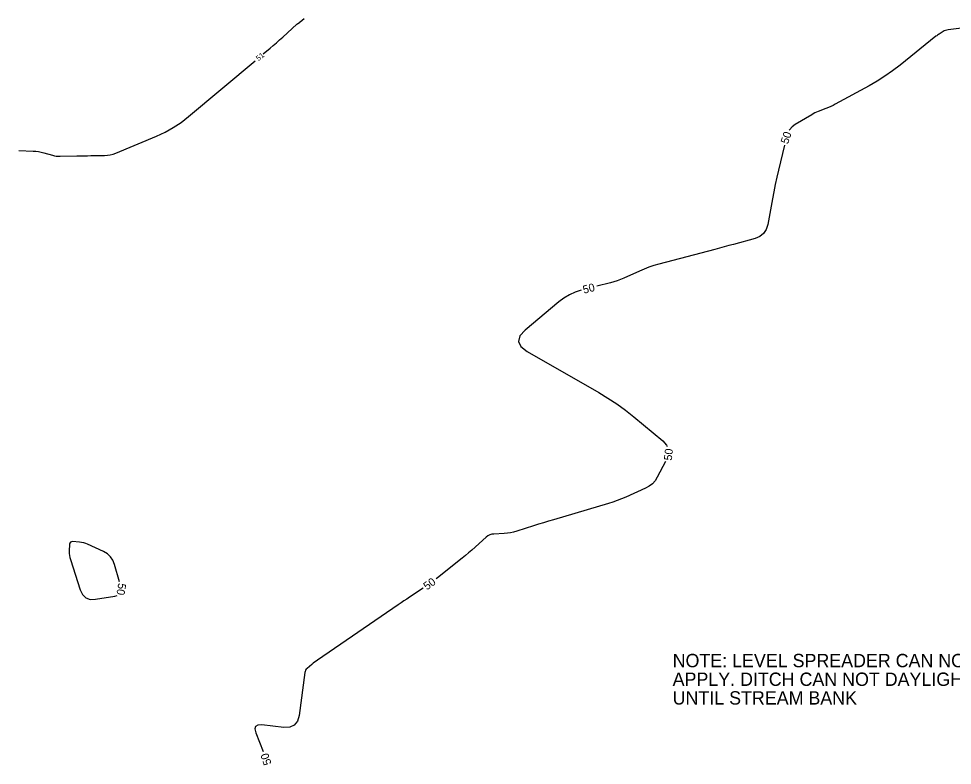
# Model space of a CAD drawing. Extents: x 2384780 to 2405861, y 547869 to 573706.
# Drawn here: x 2391215.6 to 2391565.6, y 553081.3 to 553361.3 of the extents above; entities that cross this region are included whole.
import ezdxf

# ---------------------------------------------------------------- set-up
doc = ezdxf.new("R2010")
doc.units = 0
for name, color, linetype in [('Old_Level_60', 7, 'Continuous'), ('Old_Level_61', 7, 'Continuous'), ('Old_Level_63', 7, 'Continuous')]:
    doc.layers.add(name, color=color, linetype=linetype)

msp = doc.modelspace()

# ---------------------------------------------------------------- linework, layer by layer
at = {"layer": 'Old_Level_60'}
for points in [[(2391307.291, 553348.0905), (2391309.83275, 553350.222), (2391311.03475, 553351.2415), (2391312.2255, 553352.27375), (2391313.40525, 553353.31875), (2391314.57375, 553354.3765), (2391319.89225, 553359.2445), (2391319.9475, 553359.29175), (2391320.0055, 553359.33525), (2391320.066, 553359.375), (2391320.12925, 553359.411), (2391320.34025, 553359.52175), (2391320.3845, 553359.54675), (2391320.42725, 553359.57425), (2391320.46825, 553359.60425), (2391320.5075, 553359.6365), (2391320.79875, 553359.891), (2391320.8615, 553359.945), (2391320.925, 553359.99825), (2391320.98925, 553360.05025), (2391321.05425, 553360.10175), (2391322.59075, 553361.29525)], [(2391215.58675, 553311.86225), (2391221.053, 553311.635), (2391222.0715, 553311.5625), (2391223.08025, 553311.42975), (2391224.0795, 553311.23675), (2391225.06875, 553310.98375), (2391228.2845, 553310.059), (2391228.977, 553309.88775), (2391229.6765, 553309.77), (2391230.383, 553309.70625), (2391231.0965, 553309.696), (2391237.329, 553309.84025), (2391238.6645, 553309.86925), (2391240.00025, 553309.89425), (2391241.33575, 553309.9155), (2391242.6715, 553309.933), (2391247.78925, 553309.99225), (2391248.87525, 553310.05625), (2391249.93975, 553310.22325), (2391250.98325, 553310.493), (2391252.00525, 553310.8655), (2391267.26175, 553317.25975), (2391270.462, 553318.74325), (2391273.52375, 553320.454), (2391276.447, 553322.3915), (2391279.23225, 553324.556), (2391304.22625, 553345.51975)]]:
    msp.add_lwpolyline(points, dxfattribs=at)
at = {"layer": 'Old_Level_61'}
for points in [[(2391584.9625, 553359.737), (2391564.05525, 553357.128), (2391563.53875, 553357.0355), (2391563.041, 553356.89), (2391562.56225, 553356.69075), (2391562.10225, 553356.43825), (2391560.63075, 553355.5265), (2391560.3185, 553355.3265), (2391560.01275, 553355.1175), (2391559.7135, 553354.8995), (2391559.4205, 553354.67225), (2391545.9505, 553343.90475), (2391543.1705, 553341.77775), (2391540.30725, 553339.7755), (2391537.361, 553337.8975), (2391534.3315, 553336.14375), (2391521.68175, 553329.17725), (2391520.83375, 553328.7295), (2391519.9715, 553328.31275), (2391519.095, 553327.9265), (2391518.20425, 553327.57125), (2391515.2715, 553326.46125), (2391514.6495, 553326.21), (2391514.0405, 553325.93175), (2391513.44475, 553325.6265), (2391512.86175, 553325.2945), (2391506.68025, 553321.58825), (2391505.477, 553320.7055), (2391504.5165, 553319.64525), (2391504.451, 553319.53225)], [(2391502.58975, 553313.87025), (2391500.38225, 553304.483), (2391499.7695, 553301.79875), (2391499.1915, 553299.107), (2391498.6485, 553296.40825), (2391498.1405, 553293.702), (2391496.40075, 553284.09175), (2391495.82225, 553282.22075), (2391494.83225, 553280.72675), (2391493.43075, 553279.60975), (2391491.61775, 553278.8695), (2391483.48525, 553276.64675), (2391481.74225, 553276.17225), (2391479.998, 553275.70125), (2391478.253, 553275.2335), (2391476.50725, 553274.7695), (2391455.523, 553269.21425), (2391453.6635, 553268.681), (2391451.8305, 553268.073), (2391450.024, 553267.39), (2391448.24425, 553266.63225), (2391442.47325, 553264.035), (2391441.227, 553263.50575), (2391439.96175, 553263.0305), (2391438.6775, 553262.6095), (2391437.37425, 553262.24275), (2391432.2995, 553260.9305)], [(2391426.49075, 553259.42825), (2391426.46375, 553259.42125), (2391424.18675, 553258.6985), (2391422.031, 553257.73925), (2391419.997, 553256.544), (2391418.0845, 553255.112), (2391405.4465, 553244.5335), (2391403.46, 553242.33075), (2391402.91675, 553240.25575), (2391403.8165, 553238.30875), (2391406.1595, 553236.48975), (2391433.03375, 553221.09775), (2391436.46725, 553219.0315), (2391439.80175, 553216.82225), (2391443.03675, 553214.4705), (2391446.17275, 553211.9755), (2391457.062, 553202.92175), (2391458.4665, 553201.39075), (2391458.67825, 553200.88425)], [(2391458.05225, 553195.2055), (2391454.97, 553189.351), (2391454.13575, 553188.03025), (2391453.1235, 553186.89875), (2391451.93275, 553185.95675), (2391450.564, 553185.204), (2391443.17075, 553181.8665), (2391441.576, 553181.1795), (2391439.9605, 553180.54875), (2391438.324, 553179.97425), (2391436.66675, 553179.45625), (2391416.01725, 553173.39125), (2391414.16, 553172.83925), (2391412.30625, 553172.27575), (2391410.456, 553171.7005), (2391408.60925, 553171.11375), (2391402.27525, 553169.07925), (2391401.13075, 553168.75225), (2391399.972, 553168.50175), (2391398.7995, 553168.328), (2391397.61325, 553168.23075), (2391393.7145, 553168.0385), (2391392.90575, 553167.933), (2391392.1495, 553167.69825), (2391391.44625, 553167.33475), (2391390.796, 553166.842), (2391385.41075, 553162.0335), (2391384.2495, 553161.01175), (2391383.07375, 553160.00725), (2391381.88375, 553159.01975), (2391380.67925, 553158.04925), (2391373.09375, 553152.0285), (2391372.079, 553151.2405)], [(2391234.65775, 553164.178), (2391234.5385, 553161.581), (2391234.53725, 553160.79075), (2391234.60625, 553160.01), (2391234.74525, 553159.2385), (2391234.95475, 553158.4765), (2391238.62, 553147.12975), (2391239.50075, 553145.30475), (2391240.76325, 553144.1025), (2391242.4075, 553143.52325), (2391244.4335, 553143.5665), (2391251.675, 553144.725), (2391252.4895, 553144.979)], [(2391253.38025, 553150.12375), (2391251.51975, 553156.647), (2391250.90325, 553158.20475), (2391250.01025, 553159.52525), (2391248.8405, 553160.60825), (2391247.39425, 553161.454), (2391241.44775, 553164.18225), (2391240.71525, 553164.48125), (2391239.965, 553164.71375), (2391239.19775, 553164.88), (2391238.41275, 553164.97975), (2391235.81925, 553165.19775), (2391235.33025, 553165.169), (2391234.97375, 553164.9895), (2391234.74975, 553164.65925), (2391234.65775, 553164.178)], [(2391367.2045, 553147.74425), (2391367.15, 553147.70725), (2391362.14675, 553144.38325), (2391361.076, 553143.66925), (2391360.00775, 553142.95125), (2391358.942, 553142.2295), (2391357.87875, 553141.504), (2391327.62625, 553120.78075), (2391327.06125, 553120.38375), (2391326.5065, 553119.9735), (2391325.96175, 553119.55025), (2391325.427, 553119.11375), (2391323.69625, 553117.666), (2391323.36375, 553117.3345), (2391323.108, 553116.961), (2391322.92875, 553116.545), (2391322.8265, 553116.087), (2391320.67325, 553099.9765), (2391320.063, 553097.8085), (2391318.90575, 553096.341), (2391317.2015, 553095.574), (2391314.95025, 553095.5075), (2391306.70225, 553096.435), (2391305.23625, 553096.40175), (2391304.37275, 553095.904), (2391304.11175, 553094.94225), (2391304.4535, 553093.516), (2391307.1745, 553086.49975)]]:
    msp.add_lwpolyline(points, dxfattribs=at)

# ---------------------------------------------------------------- texts
at = {"layer": 'Old_Level_60'}
msp.add_text('51', height=2, rotation=39.9882417, dxfattribs=at).set_placement((2391305.53275, 553345.31025))
at = {"layer": 'Old_Level_61'}
for rotation, p in [(71.8025528, (2391503.96375, 553314.07825)), (14.4997639, (2391427.484, 553258.13575)), (83.7080167, (2391460.3915, 553195.47)), (35.6500028, (2391368.62575, 553146.85625)), (260.1791722, (2391252.98125, 553149.7915)), (108.6497694, (2391310.41975, 553081.9385))]:
    msp.add_text('50', height=3, rotation=rotation, dxfattribs=at).set_placement(p)
at = {"layer": 'Old_Level_63'}
for s, p in [('NOTE: LEVEL SPREADER CAN NOT', (2391460.72325, 553118.086)), ('APPLY. DITCH CAN NOT DAYLIGHT', (2391460.72325, 553111.08625)), ('UNTIL STREAM BANK', (2391460.72325, 553104.08625))]:
    msp.add_text(s, height=4.9999995, dxfattribs=at).set_placement(p)

doc.saveas('drawing.dxf')
